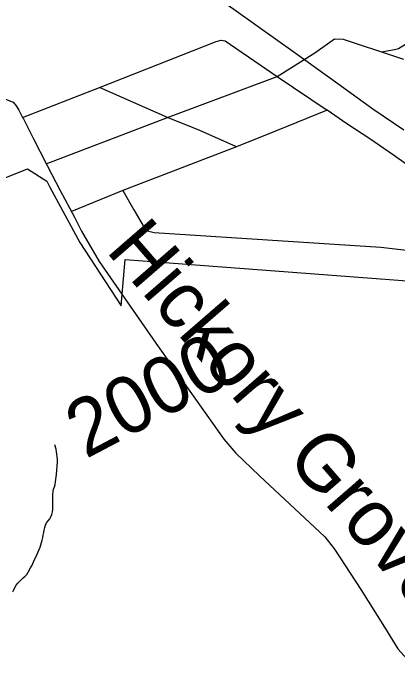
# Model space of a CAD drawing. Extents: x 1379448 to 1382868, y 593769 to 596827.
# Drawn here: x 1379836.2 to 1379935.9, y 595123.3 to 595296.5 of the extents above; entities that cross this region are included whole.
import ezdxf

# ---------------------------------------------------------------- set-up
doc = ezdxf.new("R2010")
doc.units = 0
for name, color, linetype in [('Old_Level_11', 7, 'Continuous'), ('Old_Level_32', 7, 'Continuous'), ('Old_Level_35', 7, 'Continuous'), ('Old_Level_44', 7, 'Continuous'), ('Old_Level_48', 7, 'Continuous'), ('Old_Level_49', 7, 'Continuous'), ('Old_Level_62', 7, 'Continuous'), ('Old_Level_8', 7, 'Continuous')]:
    doc.layers.add(name, color=color, linetype=linetype)

msp = doc.modelspace()

# ---------------------------------------------------------------- linework, layer by layer
at = {"layer": 'Old_Level_32'}
msp.add_lwpolyline([(1379834.14, 595274.21), (1379836.12, 595273.42), (1379836.93, 595272.49), (1379837.64, 595271.33), (1379838.6, 595269.4), (1379838.84, 595269.07), (1379841.24, 595264.27), (1379845.01, 595256.93), (1379848.37, 595250.47), (1379852.08, 595243.52), (1379853.91, 595239.94), (1379858.44, 595232.07), (1379873.2, 595210.83), (1379890.84, 595185.94), (1379893.96, 595182.29), (1379900.1, 595176.43), (1379917.01, 595160.6), (1379919.58, 595157.36), (1379926.35, 595146.93), (1379932.52, 595137.16), (1379936.02, 595131.5), (1379940.77, 595126.25)], dxfattribs=at)
at = {"layer": 'Old_Level_35'}
for p, q in [((1379931.77, 595286.43), (1379937.42, 595284.53)), ((1379876.23, 595269.45), (1379904.64, 595280.1)), ((1379904.64, 595280.1), (1379917.63, 595271.31)), ((1379838.6, 595269.4), (1379858.55, 595277.25)), ((1379876.23, 595269.45), (1379858.55, 595277.25)), ((1379894.09, 595261.85), (1379864.6, 595250.51)), ((1379864.6, 595250.51), (1379851.26, 595245.06))]:
    msp.add_line(p, q, dxfattribs=at)
for points in [[(1379858.55, 595277.25), (1379888.85, 595289.11), (1379890.1, 595289.47), (1379891.18, 595289.29), (1379904.64, 595280.1)], [(1379904.64, 595280.1), (1379914.48, 595286.19), (1379919.55, 595289.81), (1379921.81, 595289.78), (1379925.46, 595288.56), (1379931.77, 595286.43)], [(1379931.77, 595286.43), (1379935.15, 595287.04), (1379936.17, 595287.37), (1379937.96, 595288.47), (1379939.69, 595289.63)], [(1379917.63, 595271.31), (1379904.26, 595265.86), (1379894.09, 595261.85)], [(1379941.41, 595254.94), (1379934.83, 595259.69), (1379928.7, 595263.87), (1379922.72, 595267.77), (1379917.63, 595271.31)], [(1379844.76, 595257.42), (1379870.29, 595267.19), (1379876.23, 595269.45)], [(1379894.09, 595261.85), (1379884.58, 595266.02), (1379876.23, 595269.45)], [(1379864.6, 595250.51), (1379867.47, 595245.48), (1379870.11, 595240.89), (1379870.68, 595240.07), (1379872.75, 595239.6), (1379931.58, 595235.78), (1379952.31, 595233.37)]]:
    msp.add_lwpolyline(points, dxfattribs=at)
at = {"layer": 'Old_Level_44'}
for points in [[(1379937.5, 595266.13), (1379929.48, 595271.61), (1379920.39, 595278.14), (1379909.32, 595286.12), (1379894, 595297.06), (1379881.57, 595305.96), (1379866.93, 595316.98), (1379852.79, 595327.16), (1379841.11, 595335.81), (1379828.36, 595344.82), (1379813.4, 595355.58), (1379798.11, 595366.81), (1379787.48, 595374.46)], [(1379937.5, 595266.13), (1379929.48, 595271.61), (1379920.39, 595278.14), (1379909.32, 595286.12), (1379894, 595297.06)]]:
    msp.add_lwpolyline(points, dxfattribs=at)
at = {"layer": 'Old_Level_48'}
for points in [[(1379830.51, 595252.4), (1379839.9, 595256.14), (1379844.89, 595252.89), (1379845.69, 595251.35), (1379853.43, 595237.02)], [(1379853.43, 595237.02), (1379864.14, 595220.53), (1379865.2, 595232.53), (1379956.67, 595225.68)]]:
    msp.add_lwpolyline(points, dxfattribs=at)
at = {"layer": 'Old_Level_49'}
for points in [[(1379830.51, 595252.4), (1379839.9, 595256.14), (1379844.89, 595252.89), (1379845.69, 595251.35), (1379853.43, 595237.02)], [(1379853.43, 595237.02), (1379864.14, 595220.53), (1379865.2, 595232.53), (1379956.67, 595225.68)]]:
    msp.add_lwpolyline(points, dxfattribs=at)
at = {"layer": 'Old_Level_62'}
for points in [[(1379838.26, 595149.47), (1379838.75, 595149.91), (1379839.23, 595150.37), (1379839.68, 595150.84), (1379840.04, 595151.38), (1379840.68, 595152.52), (1379840.98, 595153.09), (1379841.54, 595154.28), (1379841.81, 595154.88), (1379842.09, 595155.47), (1379842.36, 595156.07), (1379842.62, 595156.68), (1379842.88, 595157.28), (1379843.12, 595157.89), (1379843.35, 595158.51), (1379843.55, 595159.13), (1379843.72, 595159.76), (1379843.85, 595160.41), (1379843.97, 595161.06), (1379844.09, 595161.71), (1379844.22, 595162.36), (1379844.36, 595163), (1379844.54, 595163.63), (1379844.8, 595164.22), (1379845.21, 595164.74), (1379845.65, 595165.25), (1379845.97, 595165.8), (1379846.18, 595166.42), (1379846.32, 595167.07), (1379846.42, 595167.72), (1379846.49, 595168.38), (1379846.49, 595169.03), (1379846.45, 595169.69), (1379846.43, 595170.35), (1379846.44, 595171), (1379846.47, 595171.66), (1379846.53, 595172.32), (1379846.62, 595172.96), (1379846.88, 595173.57), (1379847.02, 595174.21), (1379847.15, 595174.85), (1379847.26, 595175.5), (1379847.34, 595176.15), (1379847.39, 595176.81), (1379847.64, 595180.06), (1379847.62, 595180.72), (1379847.58, 595181.37), (1379847.53, 595182.03), (1379847.44, 595182.68), (1379847.29, 595183.32), (1379846.94, 595184.47)], [(1379836.03, 595146.28), (1379836.3, 595146.88), (1379836.59, 595147.47), (1379836.94, 595148.03), (1379837.33, 595148.54), (1379837.78, 595149.01), (1379838.26, 595149.47)]]:
    msp.add_lwpolyline(points, dxfattribs=at)

# ---------------------------------------------------------------- texts
at = {"layer": 'Old_Level_11'}
msp.add_text('Hickory Grove Rd.', height=14.7638, rotation=310.9193, dxfattribs=at).set_placement((1379859.96, 595234.83))
at = {"layer": 'Old_Level_32'}
msp.add_text('VICINITY MAP SHOWING LOCATION OF PROJECT B-4118', height=18, rotation=27.7977, dxfattribs=at).set_placement((1379828.68, 595001.39))
at = {"layer": 'Old_Level_8'}
msp.add_text('2000', height=14.764, rotation=27.7977, dxfattribs=at).set_placement((1379855, 595180.72))

doc.saveas('drawing.dxf')
